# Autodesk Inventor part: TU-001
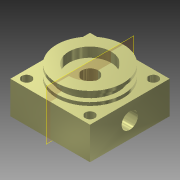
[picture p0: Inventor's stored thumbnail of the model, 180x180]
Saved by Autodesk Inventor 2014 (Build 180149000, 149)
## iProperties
Created: 2008-05
Part Number: TU-001
Document SubType Name: Modeling
Designer: PN
Density: 7.86 g/cm^3
Material: Steel, Mild
Description: Cylinder Head Cover_Back
Mass: 383.317 g
Surface Area: 134.207 cm^2
Volume: 48.7681 cm^3
Appearance: Nickel
d32: 6.000 mm
Author: PN
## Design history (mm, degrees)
sketch "Sketch1"
  geometry: L1 (-24.5, 24.5)-(24.5, 24.5); L2 (24.5, 24.5)-(24.5, -24.5); L3 (24.5, -24.5)-(-24.5, -24.5); L4 (-24.5, -24.5)-(-24.5, 24.5); 3 further points
  constraints: 8 end point, 2 midpoint, 2 parallel, 1 horizontal, 1 horizontal alignment, 1 perpendicular, 1 vertical alignment
  dimensions: "Width" = 49 distance of L1.start L1.end; "Height" = 49 distance of L3.end L1.start (= Width)
extrude "Extrusion1" new body sketch "Sketch1" distance "d2" = 20; taper "d3" = 0 deg
sketch "Sketch2"
  geometry: L1 (24.5, 24.5)-(24.5, -24.5) reference; L2 (-24.5, 24.5)-(24.5, 24.5) reference; L3 (-24.5, -24.5)-(-24.5, 24.5) reference; L4 (24.5, -24.5)-(-24.5, -24.5) reference; L5 (19.5, 19.5)-(19.5, -19.5); L6 (19.5, -19.5)-(-19.5, -19.5); L7 (-19.5, -19.5)-(-19.5, 19.5); L8 (-19.5, 19.5)-(19.5, 19.5); 1 further point
  constraints: 8 end point, 3 other
  dimensions: "d4" = 5 distance between parallel lines of L7 L3; "d5" = 39 distance of L5.end L6.end (derived); "d6" = 39 distance of L6.end L7.end (derived)
hole "Hole1" sketch "Sketch2" at (-19.5, -19.5) diameter "d7" = 6; stored, may be unused: countersink angle "d11" = 90 deg, drill point angle "d13" = 118 deg; dims "d8" = 6, "d9" = 4, "d10" = 2, "d12" = 8
pattern_linear "Rectangular Pattern1" dims "d16" = 39 (= d5), "d19" = 39 (= d6)
sketch "Sketch3"
  geometry: L1 (-24.5, 20)-(24.5, 20) reference; L2 (0, 20)-(0, 28); L3 (0, 28)-(20.5, 28); L4 (20.5, 28)-(20.5, 26); L5 (20.5, 26)-(17.5, 26); L6 (17.5, 26)-(17.5, 22); L7 (17.5, 22)-(20.5, 22); L8 (20.5, 22)-(20.5, 20); 1 further point
  constraints: 14 end point, 4 perpendicular, 2 collinear, 2 parallel, 1 midpoint, 1 point on line
  dimensions: "d25" = 8 distance of L2.start L2.end; "d26" = 20.5 distance of L2.end L3.end; "d27" = 2 distance of L3.end L4.end; "d28" = 4 distance of L5.end L6.end; "d29" = 17.5 distance between parallel lines of L6 L2
revolve "Revolution1" sketch "Sketch3" stored, may be unused: angle "d30" = 90 deg
sketch "Sketch4"
  geometry: L1 (0, -20)-(49, -20) reference; L2 (0, 0)-(0, -20) reference; L3 (24.5, -20)-(24.5, -14); 1 further point
  constraints: 2 end point, 1 midpoint, 1 parallel
  dimensions: "d32" = 6 distance of L3.start L3.end
hole "Hole2" diameter "d35" = 10; stored, may be unused: countersink angle "d39" = 90 deg, drill point angle "d41" = 0 deg; dims "d33" = 10, "d34" = 10, "d36" = 6, "d37" = 26, "d38" = 6, "d40" = 18
hole "Hole3" sketch "Sketch4" diameter "d42" = 4.134; stored, may be unused: countersink angle "d46" = 90 deg, drill point angle "d48" = 118 deg; dims "d43" = 6, "d44" = 26, "d45" = 6, "d47" = 18
sketch "Sketch6"
  geometry: L1 (0, 49)-(0, 0) reference; L2 (0, 49)-(-20, 49) reference; 4 further points
  constraints: 2 midpoint, 1 horizontal alignment, 1 vertical alignment
hole "Hole4" sketch "Sketch6" at (-10, 24.5) diameter "d49" = 10; stored, may be unused: countersink angle "d53" = 90 deg, drill point angle "d55" = 118 deg; dims "d50" = 6, "d51" = 26, "d52" = 6, "d54" = 10
mirror "Mirror1"
body "Solid1"
